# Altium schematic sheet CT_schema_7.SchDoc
size 371 x 336 mm
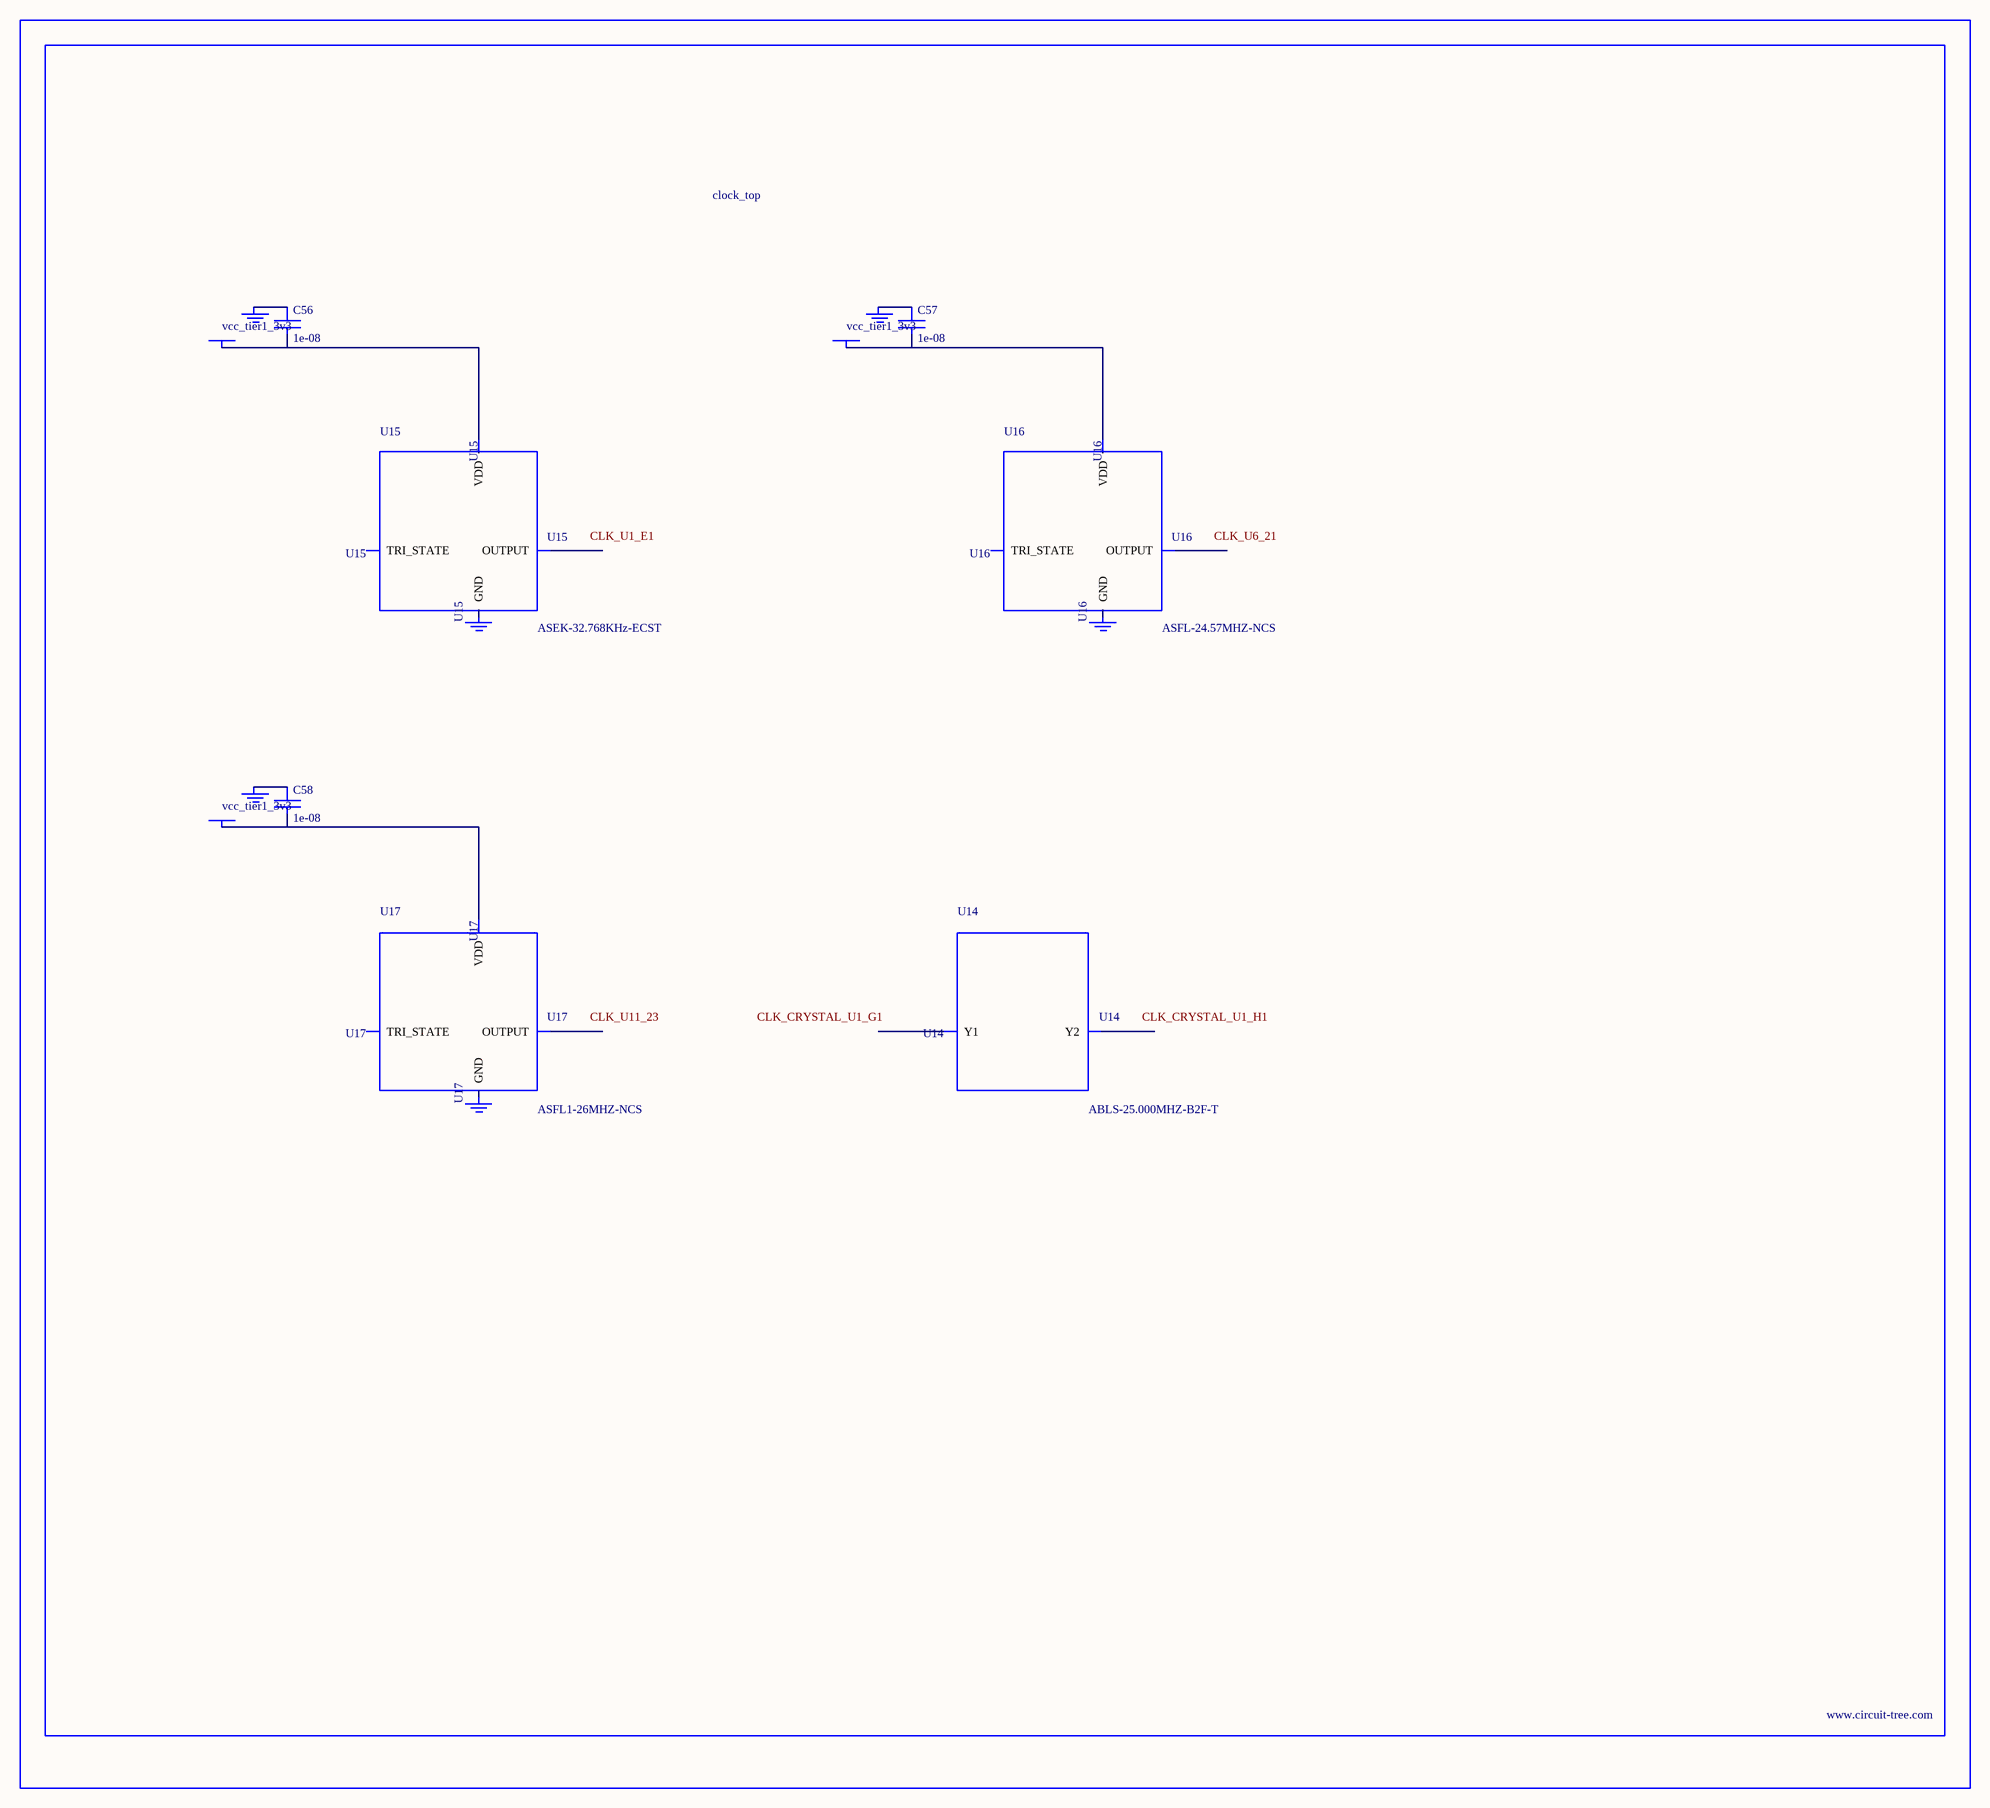
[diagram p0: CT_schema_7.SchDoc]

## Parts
BORDER6  (no value)
C56  1e-08  [C0402]
C57  1e-08  [C0402]
C58  1e-08  [C0402]
GND_INSTANCE_6_0  (no value)
GND_INSTANCE_6_1  (no value)
GND_INSTANCE_6_2  (no value)
GND_INSTANCE_6_3  (no value)
GND_INSTANCE_6_4  (no value)
GND_INSTANCE_6_5  (no value)
POWER_INSTANCE_6_0  vcc_tier1_3v3
POWER_INSTANCE_6_1  vcc_tier1_3v3
POWER_INSTANCE_6_2  vcc_tier1_3v3
U14  ABLS-25.000MHZ-B2F-T  [ABLS-25.000MHZ-B2F-T]
U15  ASEK-32.768KHz-ECST  [ASEK]
U16  ASFL-24.57MHZ-NCS  [ASFL1]
U17  ASFL1-26MHZ-NCS  [ASFL1]

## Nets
NetC56_1: C56.1 GND_INSTANCE_6_0.0(GND)
NetC56_2: C56.2 POWER_INSTANCE_6_0.0(PWR) U15.4(VDD)
NetC57_1: C57.1 GND_INSTANCE_6_2.0(GND)
NetC57_2: C57.2 POWER_INSTANCE_6_1.0(PWR) U16.4(VDD)
NetC58_1: C58.1 GND_INSTANCE_6_4.0(GND)
NetC58_2: C58.2 POWER_INSTANCE_6_2.0(PWR) U17.4(VDD)

Not connected (* = marked no-connect by the designer): GND_INSTANCE_6_1 0(GND); GND_INSTANCE_6_3 0(GND); GND_INSTANCE_6_5 0(GND); U14 1(Y1) 2(Y2); U15 1(TRI_STATE) 2(GND) 3(OUTPUT); U16 1(TRI_STATE) 2(GND) 3(OUTPUT); U17 1(TRI_STATE) 2(GND) 3(OUTPUT)

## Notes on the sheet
- Labels drawn without touching a wire or pin: CLK_CRYSTAL_U1_G1, CLK_CRYSTAL_U1_H1, CLK_U1_E1, CLK_U6_21, CLK_U11_23

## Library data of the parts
BORDER6 = BORDER_PAGE6
C56-C58 = C0402C103K3RAC
GND_INSTANCE_6_0-GND_INSTANCE_6_5 = GND
POWER_INSTANCE_6_0-POWER_INSTANCE_6_2 = PWR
